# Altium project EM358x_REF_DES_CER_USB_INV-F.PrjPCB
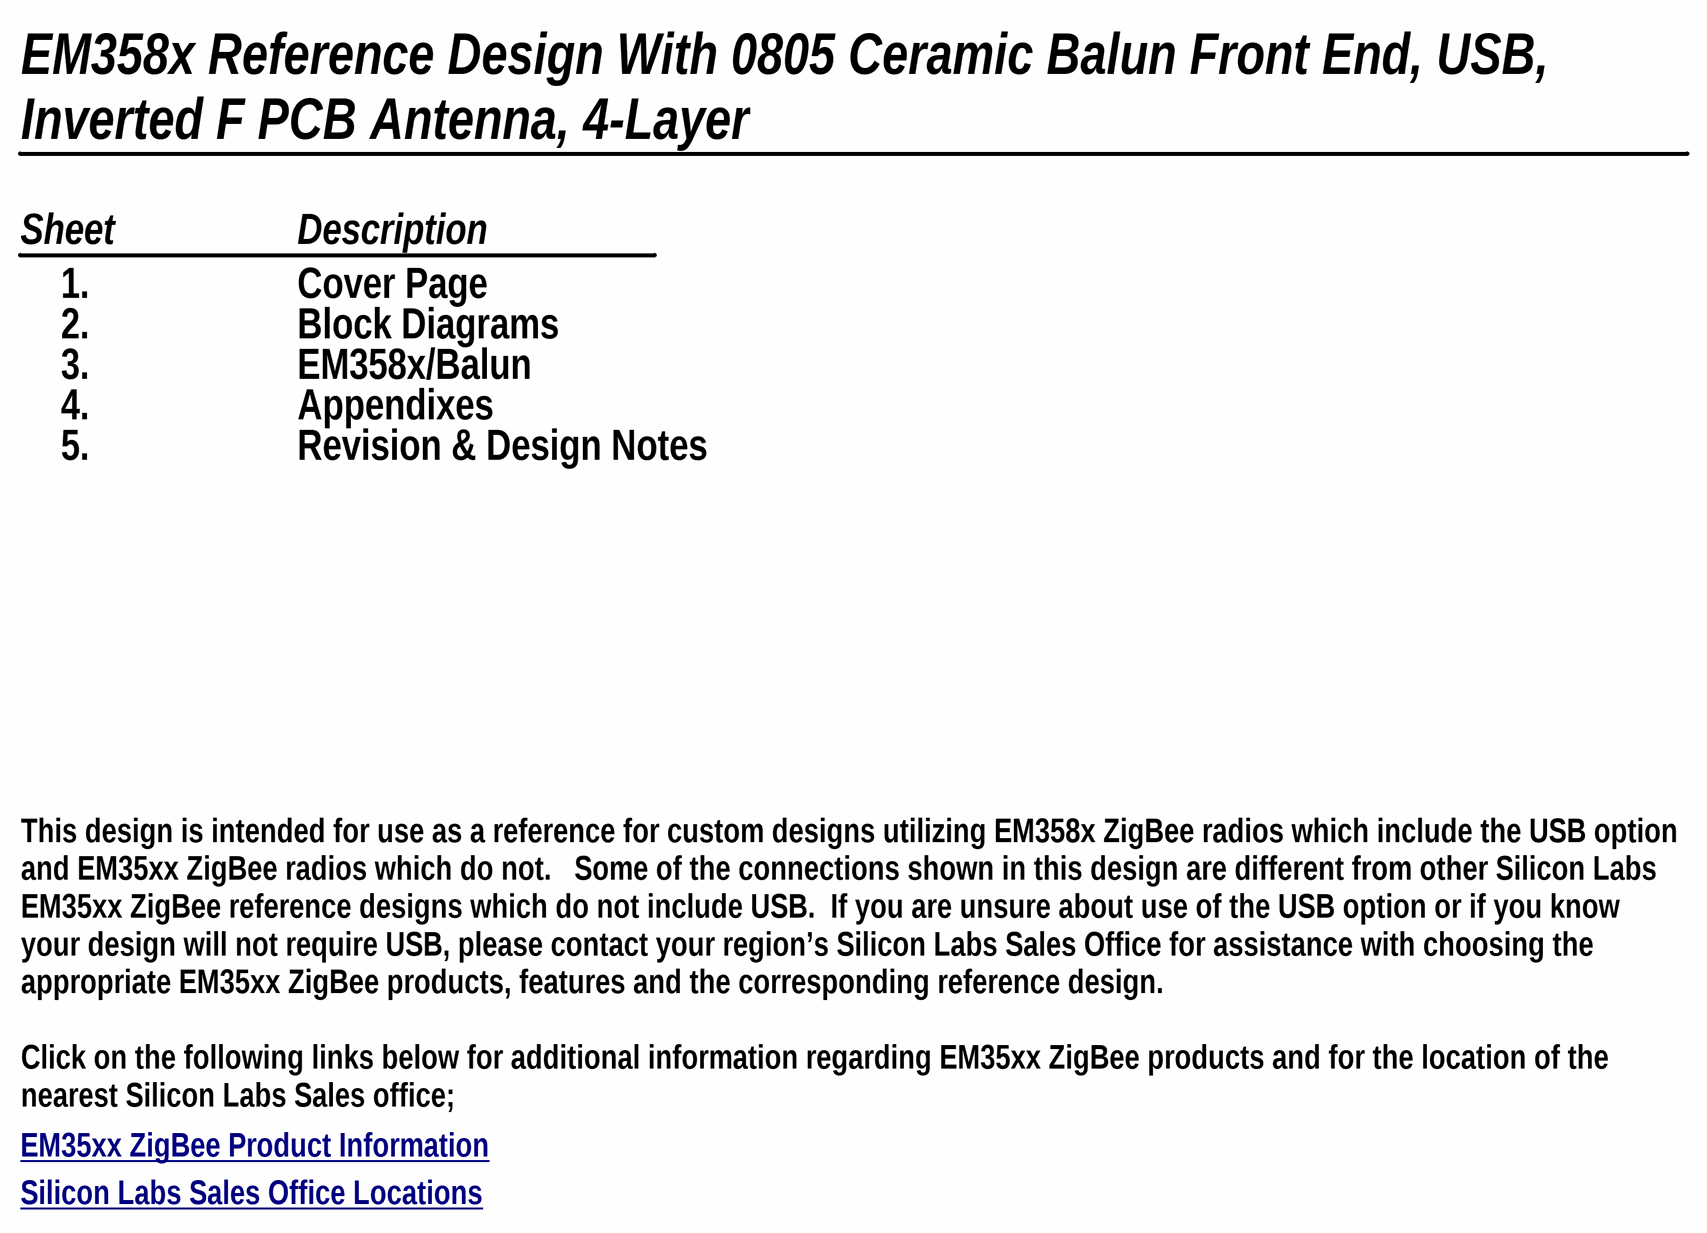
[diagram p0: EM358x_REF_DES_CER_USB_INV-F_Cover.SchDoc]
Title: Ceramic Balun W/USB 4 Layer Ref.Design; Company Web Site: www.silabs.com; Company Tel: 617-951-0200; Company Design Group: Embedded Systems Applications Engineering Group; Company Address 3: Boston, MA 02210; Company Address 2: 2nd Floor; Company Address 1: 25 Thomson Place; ClassName: PCB Only; Board Rev: A0; Board No: EM358x_REF_DES_CER_USB_INV-F
5 sheets, 71 parts. Net scope: global (net labels, ports and power ports of the same name join across sheets).
Board file: EM358x_REF_DES_CER_USB_INV-F.PcbDoc
Sheets:
  EM358x_REF_DES_CER_USB_INV-F_Cover.SchDoc
  EM358x_REF_DES_CER_USB_INV-F_Block.SchDoc
  EM358x_REF_DES_CER_USB_INV-F_Main.SchDoc
  EM358x_REF_DES_CER_USB_INV-F_App.SchDoc
  EM358x_REF_DES_CER_USB_INV-F_Rev_Notes.SchDoc

## Sheet EM358x_REF_DES_CER_USB_INV-F_Cover.SchDoc: EM358x/0805 Ceramic Balun W/USB Reference Design
size C; Organization: MCU & Wireless Division Simplicity Support Group; Address1: 25 Thomson Place, 2nd Floor; Address2: Boston, MA 02210, USA; Address3: www.silabs.com; Address4: 617-951-0200; Revision: A0; SheetNumber: 1; SheetTotal: 5

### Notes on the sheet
- EM358x Reference Design With 0805 Ceramic Balun Front End, USB, Inverted F PCB Antenna, 4-Layer
- Sheet
- 1.
- Description
- Cover Page
- 2.
- Block Diagrams
- 3.
- 4.
- EM358x/Balun
- Appendixes
- 5.
- Revision & Design Notes
- This design is intended for use as a reference for custom designs utilizing EM358x ZigBee radios which include the USB option and EM35xx ZigBee radios which do not.   Some of the connections shown in this design are different from other Silicon Labs EM35xx ZigBee reference designs which do not include USB.  If you are unsure about use of the USB option or if you know your design will not require USB, please contact your region’s Silicon Labs Sales Office for assistance with choosing the appropriate EM35xx ZigBee products, features and the corresponding reference design.
  Click on the following links below for additional information regarding EM35xx ZigBee products and for the location of the nearest Silicon Labs Sales office;
- EM35xx ZigBee Product Information <http://www.silabs.com/products/wireless/zigbee/Pages/default.aspx>
- Silicon Labs Sales Office Locations <http://www.silabs.com/buysample/pages/contact-sales.aspx>

## Sheet EM358x_REF_DES_CER_USB_INV-F_Block.SchDoc: EM358x/0805 Ceramic Balun W/USB Reference Design
size C; Organization: MCU & Wireless Division Simplicity Support Group; Address1: 25 Thomson Place, 2nd Floor; Address2: Boston, MA 02210, USA; Address3: www.silabs.com; Address4: 617-951-0200; Revision: A0; SheetNumber: 2; SheetTotal: 5
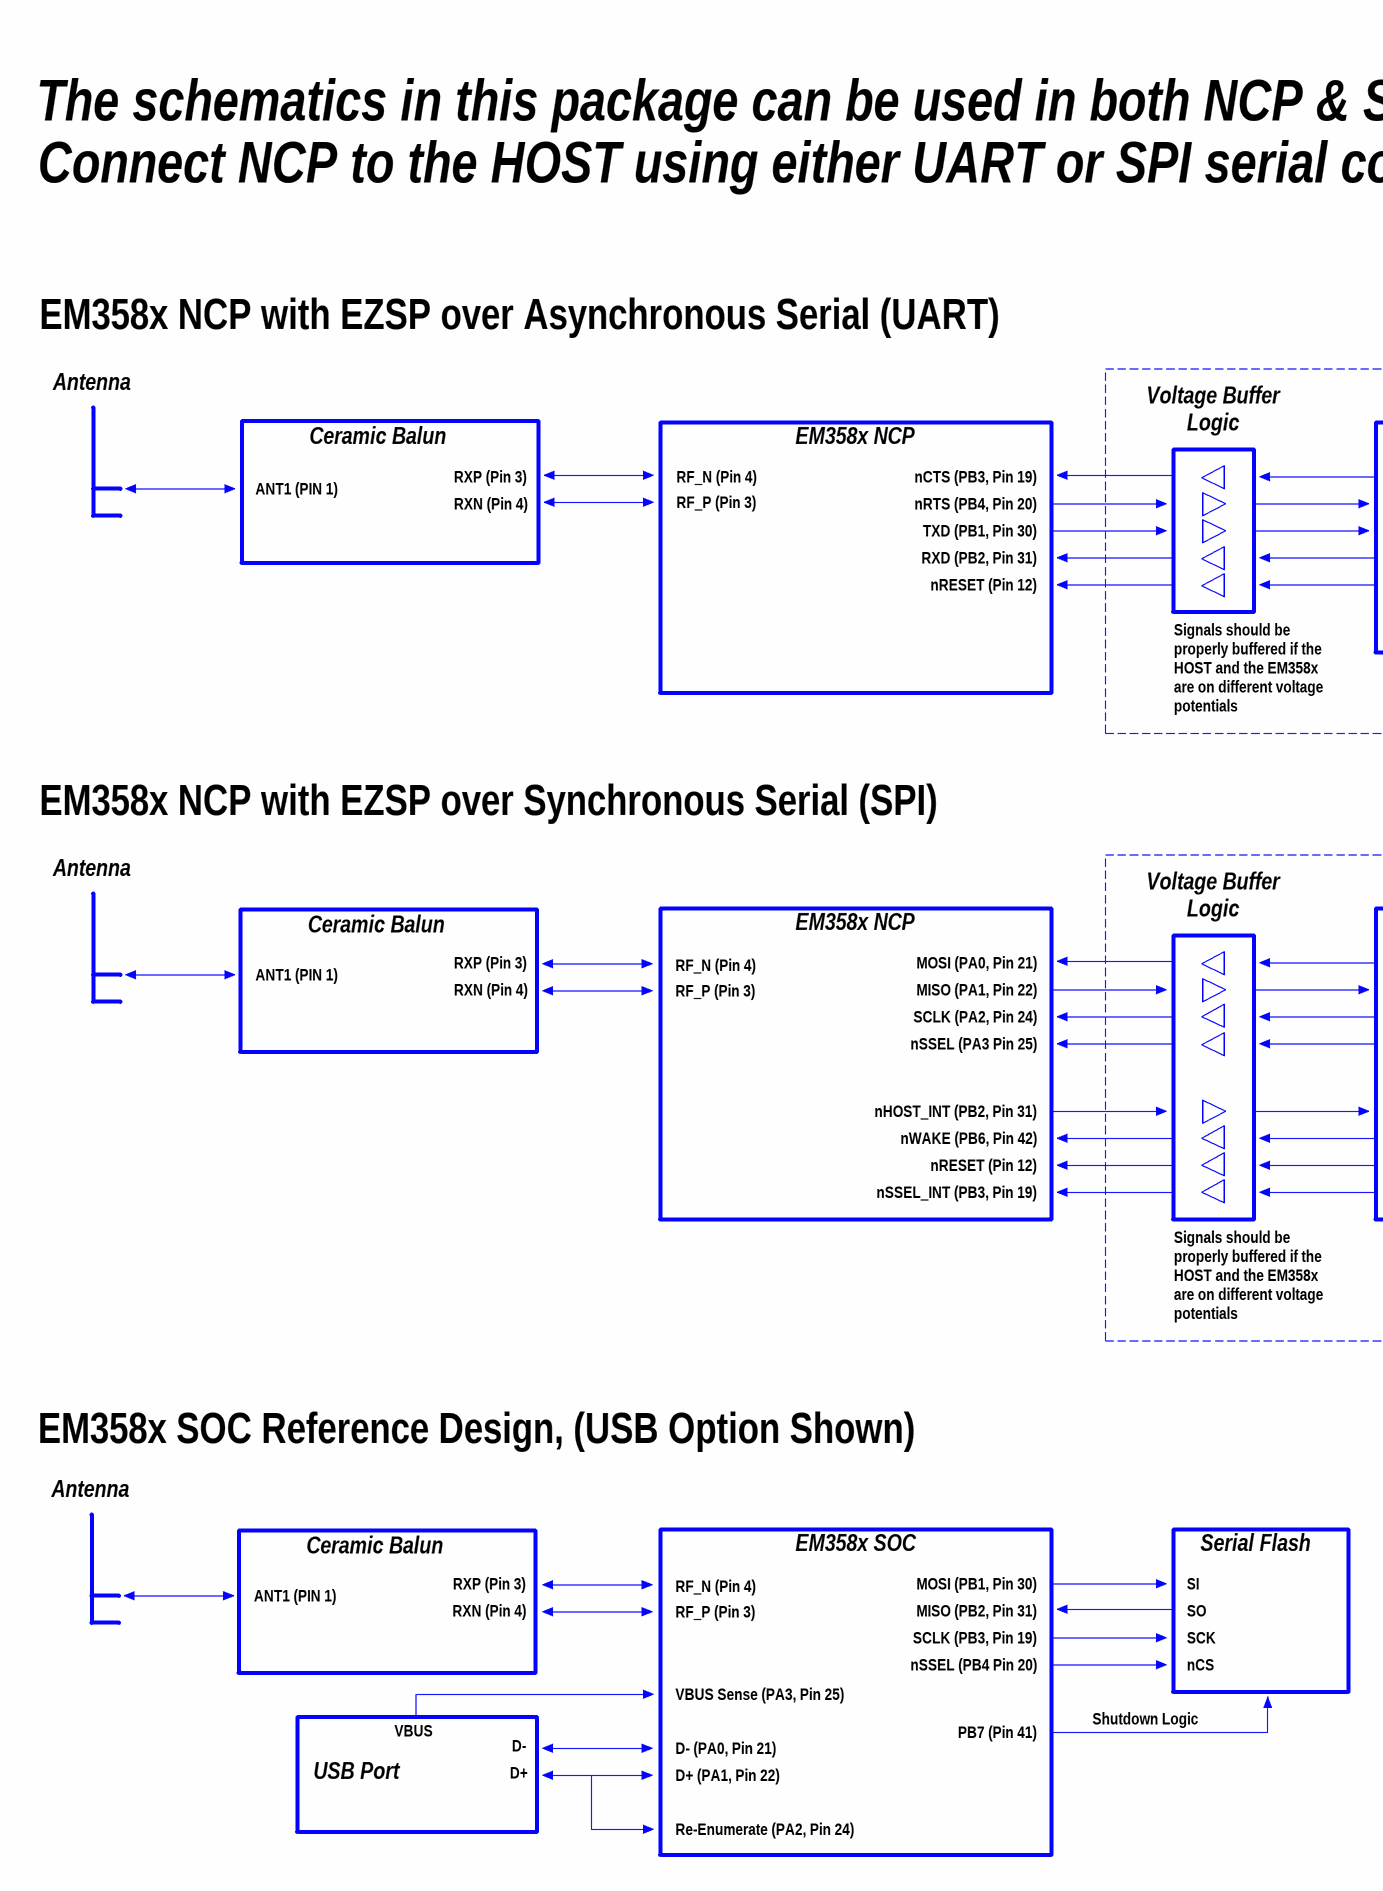
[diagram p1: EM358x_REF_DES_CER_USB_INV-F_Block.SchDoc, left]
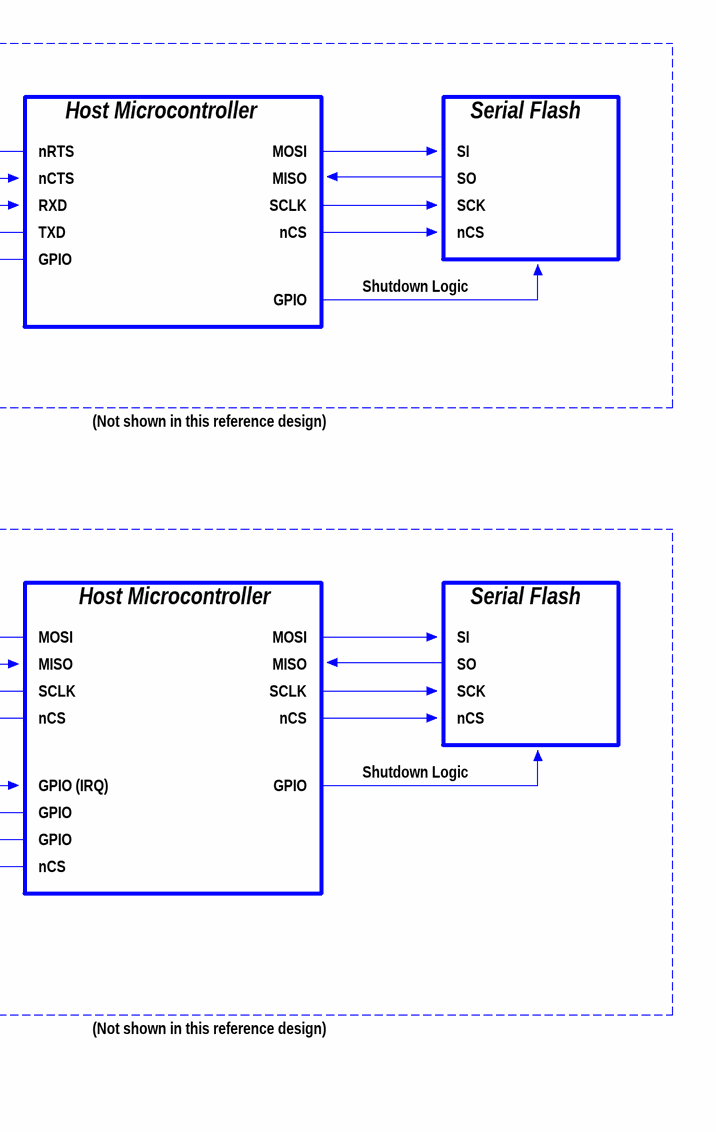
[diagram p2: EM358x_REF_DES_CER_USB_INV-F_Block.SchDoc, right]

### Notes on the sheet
- The schematics in this package can be used in both NCP & SOC designs involving the EM358x.
- Connect NCP to the HOST using either UART or SPI serial connection as shown below.
- EM358x NCP with EZSP over Asynchronous Serial (UART)
- Antenna
- Voltage Buffer
- Logic
- ANT1 (PIN 1)
- Ceramic Balun
- RXP (Pin 3)
- RF_N (Pin 4)
- EM358x NCP
- nCTS (PB3, Pin 19)
- nRTS
- Host Microcontroller
- MOSI
- SI
- Serial Flash
- RXN (Pin 4)
- RF_P (Pin 3)
- nRTS (PB4, Pin 20)
- TXD (PB1, Pin 30)
- RXD (PB2, Pin 31)
- nCTS
- RXD
- TXD
- MISO
- SCLK
- nCS
- SO
- SCK
- nRESET (Pin 12)
- GPIO
- Shutdown Logic
- Signals should be properly buffered if the HOST and the EM358x are on different voltage potentials
- (Not shown in this reference design)
- EM358x NCP with EZSP over Synchronous Serial (SPI)
- MOSI (PA0, Pin 21)
- MISO (PA1, Pin 22)
- SCLK (PA2, Pin 24)
- nSSEL (PA3 Pin 25)
- nHOST_INT (PB2, Pin 31)
- nWAKE (PB6, Pin 42)
- GPIO (IRQ)
- nSSEL_INT (PB3, Pin 19)
- EM358x SOC Reference Design, (USB Option Shown)
- EM358x SOC
- MOSI (PB1, Pin 30)
- MISO (PB2, Pin 31)
- SCLK (PB3, Pin 19)
- VBUS Sense (PA3, Pin 25)
- nSSEL (PB4 Pin 20)
- USB Port
- VBUS
- D-
- D+
- D- (PA0, Pin 21)
- D+ (PA1, Pin 22)
- PB7 (Pin 41)
- Re-Enumerate (PA2, Pin 24)

## Sheet EM358x_REF_DES_CER_USB_INV-F_Main.SchDoc: EM358x/0805 Ceramic Balun W/USB Reference Design
size C; Organization: MCU & Wireless Division Simplicity Support Group; Address1: 25 Thomson Place, 2nd Floor; Address2: Boston, MA 02210, USA; Address3: www.silabs.com; Address4: 617-951-0200; Revision: A0; SheetNumber: 3; SheetTotal: 5
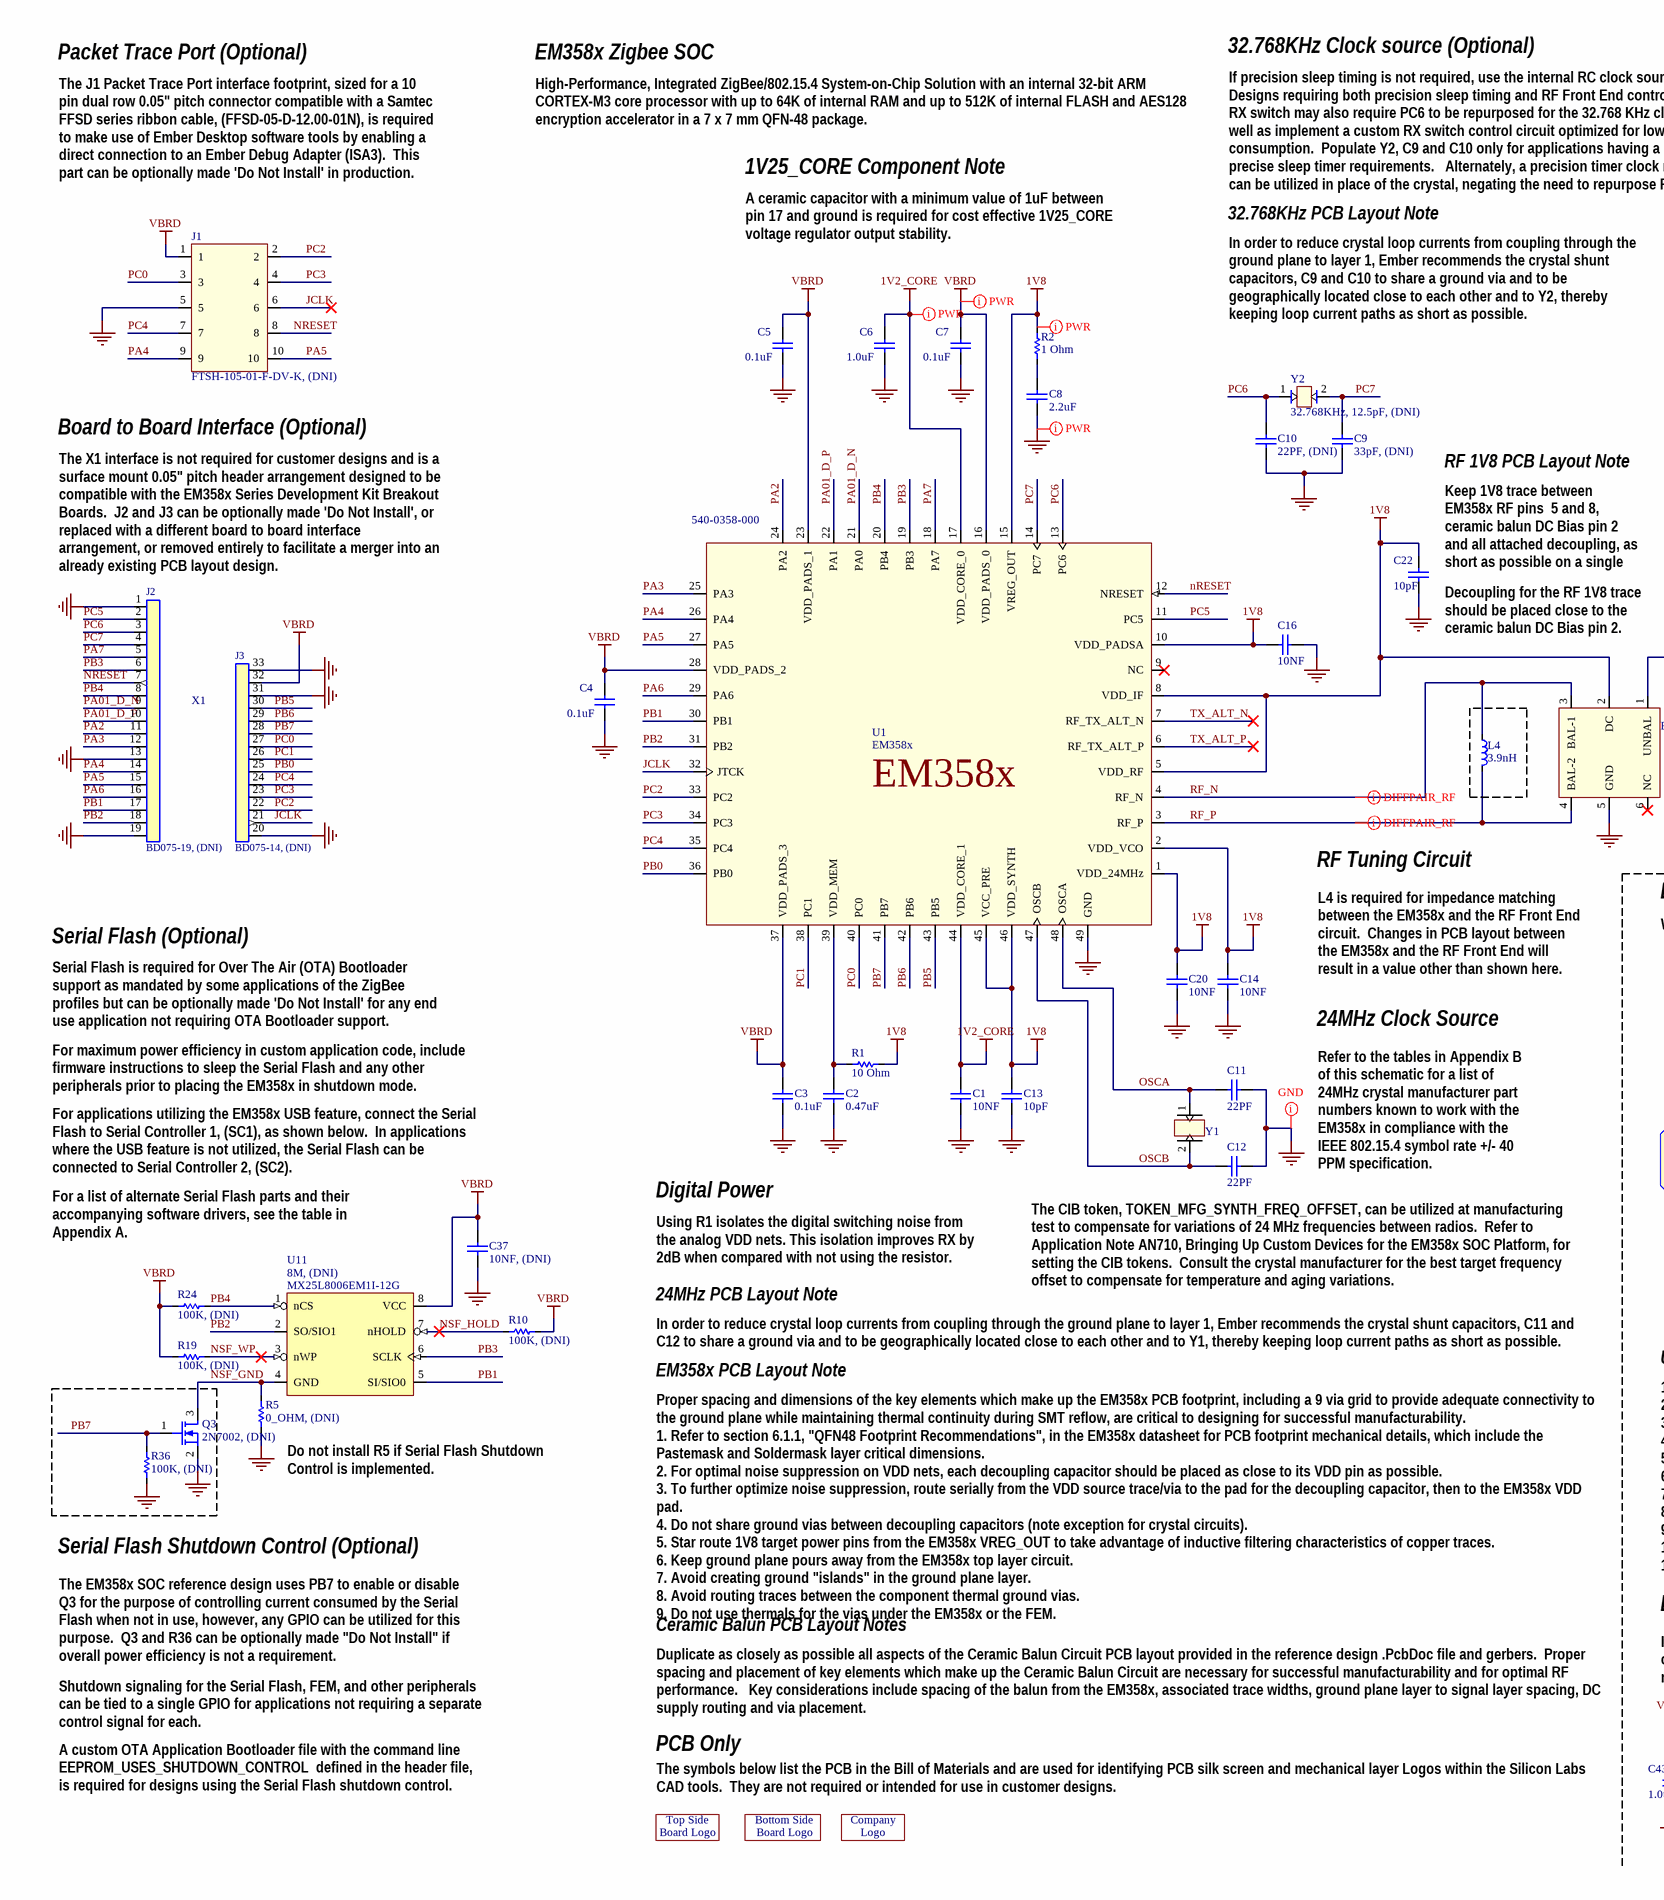
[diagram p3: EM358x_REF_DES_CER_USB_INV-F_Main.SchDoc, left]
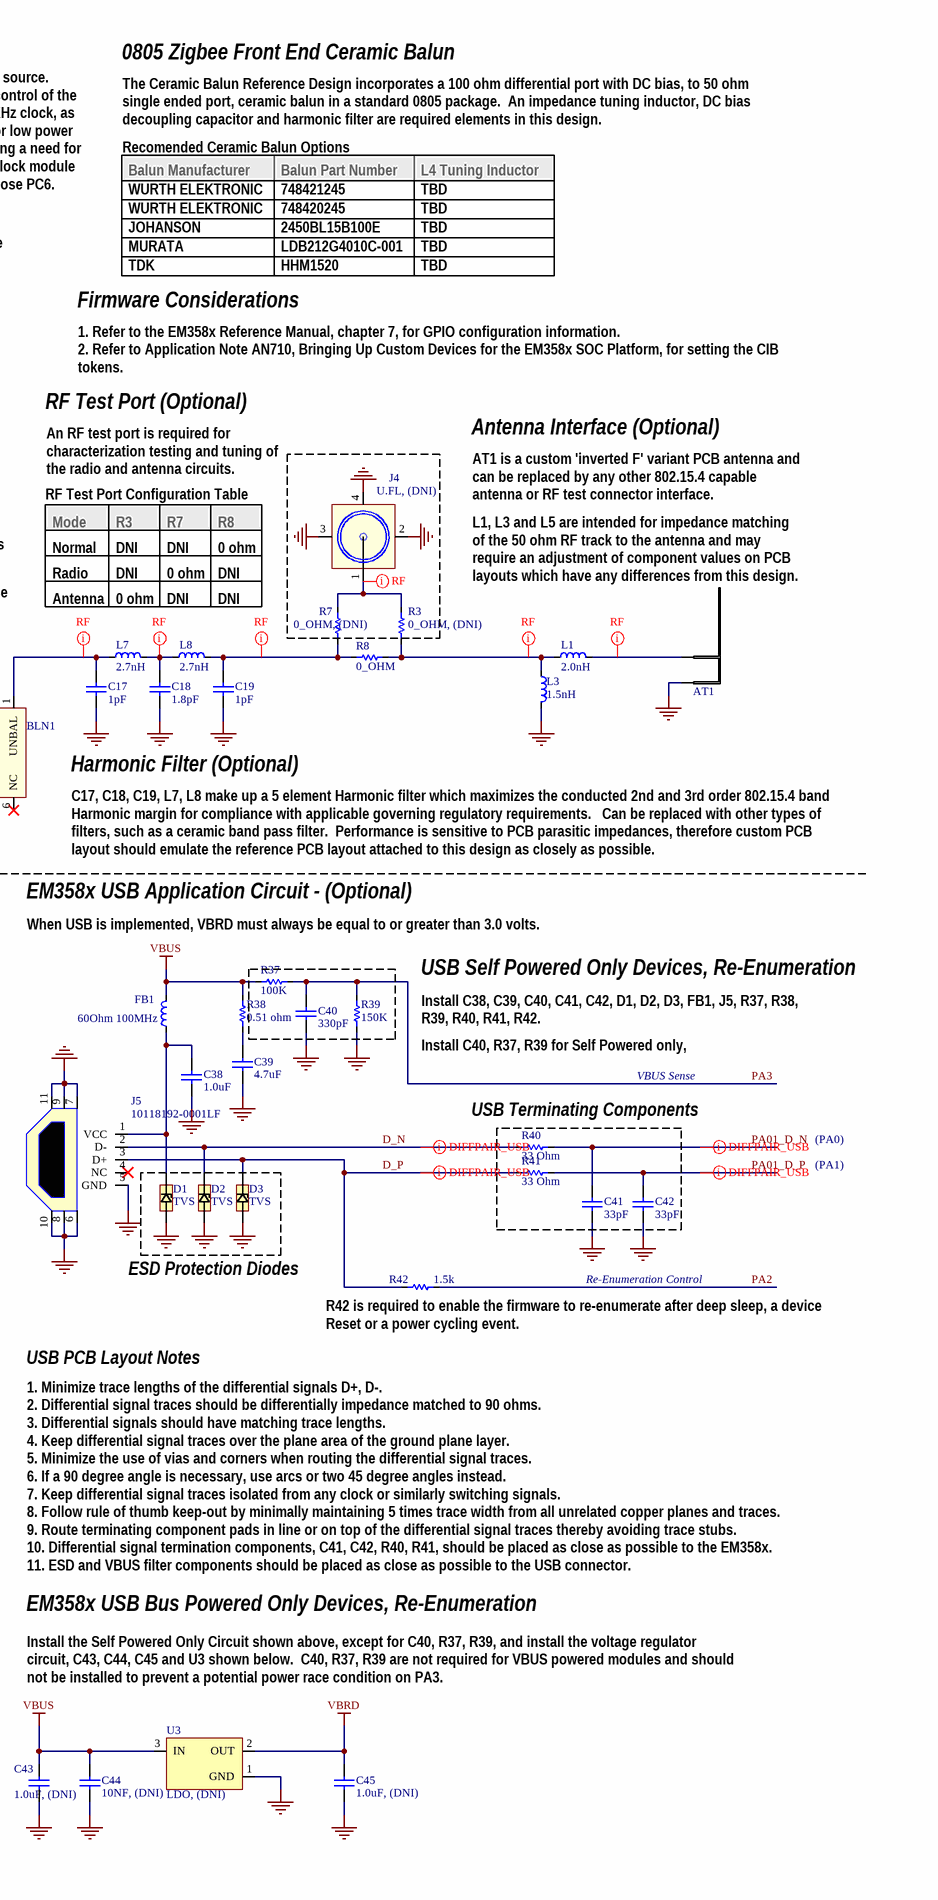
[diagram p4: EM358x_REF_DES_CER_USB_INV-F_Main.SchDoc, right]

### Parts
AT1  Copper Trace  [INVERTED_F_062_SM]  (value not drawn)  (no BOM)
BLN1  CHIP MULTILAYER CERAMIC, 2.4 GHZ. 50/100 Ohm  [BLN_0805]  (value not drawn)
C1  10NF  [C_0402]
C2  0.47uF  [C_0402]
C3  0.1uF  [C_0402]
C4  0.1uF  [C_0402]
C5  0.1uF  [C_0402]
C6  1.0uF  [C_0603]
C7  0.1uF  [C_0402]
C8  2.2uF  [C_0603]
C9  33pF, (DNI)  [C_0402]
C10  22PF, (DNI)  [C_0402]
C11  22PF  [C_0402]
C12  22PF  [C_0402]
C13  10pF  [C_0402]
C14  10NF  [C_0402]
C16  10NF  [C_0402]
C17  1pF  [C_0402]
C18  1.8pF  [C_0402]
C19  1pF  [C_0402]
C20  10NF  [C_0402]
C22  10pF  [C_0402]
C37  10NF, (DNI)  [C_0402]
C38  1.0uF  [C_0603]
C39  4.7uF  [C_0603]
C40  330pF  [C_0402]
C41  33pF  [C_0402]
C42  33pF  [C_0402]
C43  1.0uF, (DNI)  [C_0603]
C44  10NF, (DNI)  [C_0402]
C45  1.0uF, (DNI)  [C_0603]
D1  TVS  [TVS_0402]
D2  TVS  [TVS_0402]
D3  TVS  [TVS_0402]
FB1  60Ohm 100MHz  [L_0603]
J1  FTSH-105-01-F-DV-K, (DNI)  [610-0019-000-REF-DES]
J2  BD075-19, (DNI)  (mechanical)
J3  BD075-14, (DNI)  (mechanical)
J4  U.FL, (DNI)  [UFL-R-SMT_1]
J5  10118192-0001LF  [FCI_10118192-0001LF]
L1  2.0nH  [L_0402]
L3  1.5nH  [L_0402]
L4  3.9nH  [L_0603]
L7  2.7nH  [L_0402]
L8  2.7nH  [L_0402]
LOGO1  SiliconLabsLogo_100  [SiliconLabsLogo_100_Mech-16]  (value not drawn)  (no BOM)
PCB1  EM35x Ceramic Balun 4 Layer Reference Design w/USB, Inverted F, Corporate Logo  [710-0651-006]  (value not drawn)
PCB2  Bottom Silk Screen ID and RoHS Text  [710-0651-006_ROHS]  (value not drawn)  (no BOM)
Q3  2N7002, (DNI)  [SOT23-3L]
R1  10 Ohm  [R_0402]
R2  1 Ohm  [R_0402]
R3  0_OHM, (DNI)  [R_0402]
R5  0_OHM, (DNI)  [R_0402]
R7  0_OHM, (DNI)  [R_0402]
R8  0_OHM  [R_0402]
R10  100K, (DNI)  [R_0402]
R19  100K, (DNI)  [R_0402]
R24  100K, (DNI)  [R_0402]
R36  100K, (DNI)  [R_0402]
R37  100K  [R_0402]
R38  0.51 ohm  [R_0402]
R39  150K  [R_0402]
R40  33 Ohm  [R_0402]
R41  33 Ohm  [R_0402]
R42  1.5k  [R_0402]
U1  EM358x  PART_NUMBER: 540-0358-000  [EM357]
U3  LDO, (DNI)  [TSOP95P280X90-3N]
U11  8M, (DNI)  Part: MX25L8006EM1I-12G  [SOIC127P600-8M]
X1  Dual Row Socket, (DNI)  [EM35X_RCM_MODULE_SIDE_SMT]  (value not drawn)  (no BOM)
Y1  24.000MHZ, 18PF LOAD  [HC-49-SMD]  (value not drawn)
Y2  32.768KHz, 12.5pF, (DNI)  [IL3X]

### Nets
1V2_CORE: C1.1 C6.1 U1.17(VDD_CORE_0) U1.44(VDD_CORE_1)
1V8: BLN1.2(DC) C13.1 C14.1 C16.1 C20.1 C22.1 R1.1 R2.1 U1.1(VDD_24MHz) U1.2(VDD_VCO) U1.5(VDD_RF) U1.8(VDD_IF) U1.10(VDD_PADSA) U1.15(VREG_OUT) U1.45(VCC_PRE) U1.46(VDD_SYNTH)
GND: AT1.2(GND) BLN1.5(GND) C1.2 C2.2 C3.2 C4.2 C5.2 C6.2 C7.2 C8.2 C9.2 C10.2 C11.2 C12.2 C13.2 C14.2 C16.2 C17.2 C18.2 C19.2 C20.2 C22.2 C37.2 C38.2 C39.2 C40.2 C41.2 C42.2 C43.2 C44.2 C45.2 D1.1 D2.1 D3.1 J1.5 J4.2(GND) J4.3(GND) J4.4(GND) J5.5(GND) J5.6 J5.7 J5.8 J5.9 J5.10 J5.11 L3.2 Q3.2(S) R5.2 R36.2 R39.2 U1.49(GND) U3.1(GND) X1.1(GND) X1.13(GND) X1.19(GND) X1.20(GND) X1.31(GND) X1.33(GND)
VBRD: C3.1 C4.1 C5.1 C7.1 C37.1 C45.1 J1.1 R10.2 R19.2 R24.2 U1.16(VDD_PADS_0) U1.23(VDD_PADS_1) U1.28(VDD_PADS_2) U1.37(VDD_PADS_3) U3.2(OUT) U11.8(VCC) X1.32(VBRD)
VBUS: C43.1 C44.1 FB1.2 R37.1 R38.2 U3.3(IN)
D_N: D2.2 J5.2(D-) R40.1
D_P: D3.2 J5.3(D+) R41.1 R42.1
JCLK: J1.6 U1.32(JTCK) X1.21(JCLK)
nRESET: J1.8 U1.12(NRESET) X1.7(nRESET)
NSF_GND: Q3.3(D) R5.1 U11.4(GND)
NSF_HOLD: R10.1 U11.7(nHOLD)
NSF_WP: R19.1 U11.3(nWP)
OSCA: C11.1 U1.48(OSCA) Y1.1(OSCB)
OSCB: C12.1 U1.47(OSCB) Y1.2(OSCA)
PA01_D_N: C41.1 R40.2 U1.21(PA0) X1.9(PA0)
PA01_D_P: C42.1 R41.2 U1.22(PA1) X1.10(PA1)
PA2: R42.2 U1.24(PA2) X1.11(PA2)
PA3: C40.1 R37.2 R39.1 U1.25(PA3) X1.12(PA3)
PA4: J1.9 U1.26(PA4) X1.14(PA4)
PA5: J1.10 U1.27(PA5) X1.15(PA5)
PA6: U1.29(PA6) X1.16(PA6)
PA7: U1.18(PA7) X1.5(PA7)
PB0: U1.36(PB0) X1.25(PB0)
PB1: U1.30(PB1) U11.5(SI/SIO0) X1.17(PB1)
PB2: U1.31(PB2) U11.2(SO/SIO1) X1.18(PB2)
PB3: U1.19(PB3) U11.6(SCLK) X1.6(PB3)
PB4: R24.1 U1.20(PB4) U11.1(nCS) X1.8(PB4)
PB5: U1.43(PB5) X1.30(PB5)
PB6: U1.42(PB6) X1.29(PB6)
PB7: Q3.1(G) R36.1 U1.41(PB7) X1.28(PB7)
PC0: J1.3 U1.40(PC0) X1.27(PC0)
PC1: U1.38(PC1) X1.26(PC1)
PC2: J1.2 U1.33(PC2) X1.22(PC2)
PC3: J1.4 U1.34(PC3) X1.23(PC3)
PC4: J1.7 U1.35(PC4) X1.24(PC4)
PC5: U1.11(PC5) X1.2(PC5)
PC6: C10.1 U1.13(PC6) X1.3(PC6) Y2.1
PC7: C9.1 U1.14(PC7) X1.4(PC7) Y2.2
RF_N: BLN1.3(BAL-1) L4.1 U1.4(RF_N)
RF_P: BLN1.4(BAL-2) L4.2 U1.3(RF_P)
TX_ALT_N: U1.7(RF_TX_ALT_N)
TX_ALT_P: U1.6(RF_TX_ALT_P)
NetAT1_1: AT1.1(ANT) L1.2
NetBLN1_1: BLN1.1(UNBAL) C17.1 L7.1
NetC2_1: C2.1 R1.2 U1.39(VDD_MEM)
NetC8_1: C8.1 R2.2
NetC18_1: C18.1 L7.2 L8.1
NetC19_1: C19.1 L8.2 R7.1 R8.1
NetC38_1: C38.1 D1.2 FB1.1 J5.1(VCC)
NetC39_1: C39.1 R38.1
NetJ4_1: J4.1(SIGNAL) R3.2 R7.2
NetL1_1: L1.1 L3.1 R3.1 R8.2

Not connected (* = marked no-connect by the designer): BLN1 6(NC)*; J5 4(NC)*; U1 9(NC)*

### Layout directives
rule Width Constraint [Pref Width = 20mil    Min Width = 5mil    Max Width = 40mil]: 1V2_CORE, 1V8, VBRD
rule Width Constraint [Pref Width = 28mil    Min Width = 6mil    Max Width = 60mil]; rule Clearance Constraint [Clearance = 6mil]: NetAT1_1, NetBLN1_1, NetC18_1, NetC19_1, NetJ4_1, NetL1_1
differential pair; rule Width Constraint [Pref Width = 7mil    Min Width = 5mil    Max Width = 10mil]; rule Matched Net Lengths [Tolerance = 2.5mil]: RF_N, RF_P
rule Clearance Constraint [Clearance = 9.5mil]: GND
rule Width Constraint [Pref Width = 20mil    Min Width = 5mil    Max Width = 40mil]; rule Short-Circuit Constraint [Short Circuit - Allowed]: GND
rule Differential Pairs Routing [Pref Gap = 9mil    Min Gap  = 8mil    Max Gap  = 50mil]; rule Matched Net Lengths [Tolerance = 100mil]; differential pair; rule Width Constraint [Pref Width = 12mil    Min Width = 6mil    Max Width = 60mil]: D_N, D_P, PA01_D_N, PA01_D_P

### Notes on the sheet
- Packet Trace Port (Optional)
- EM358x Zigbee SOC
- 32.768KHz Clock source (Optional)
- 0805 Zigbee Front End Ceramic Balun
- High-Performance, Integrated ZigBee/802.15.4 System-on-Chip Solution with an internal 32-bit ARM CORTEX-M3 core processor with up to 64K of internal RAM and up to 512K of internal FLASH and AES128 encryption accelerator in a 7 x 7 mm QFN-48 package.
- The Ceramic Balun Reference Design incorporates a 100 ohm differential port with DC bias, to 50 ohm single ended port, ceramic balun in a standard 0805 package.  An impedance tuning inductor, DC bias decoupling capacitor and harmonic filter are required elements in this design.
- Recomended Ceramic Balun Options
- The J1 Packet Trace Port interface footprint, sized for a 10 pin dual row 0.05" pitch connector compatible with a Samtec FFSD series ribbon cable, (FFSD-05-D-12.00-01N), is required to make use of Ember Desktop software tools by enabling a direct connection to an Ember Debug Adapter (ISA3).  This part can be optionally made 'Do Not Install' in production.
- 1V25_CORE Component Note
- If precision sleep timing is not required, use the internal RC clock source.  Designs requiring both precision sleep timing and RF Front End control of the RX switch may also require PC6 to be repurposed for the 32.768 KHz clock, as well as implement a custom RX switch control circuit optimized for low power consumption.  Populate Y2, C9 and C10 only for applications having a need for precise sleep timer requirements.   Alternately, a precision timer clock module can be utilized in place of the crystal, negating the need to repurpose PC6.
- WURTH ELEKTRONIC
- Balun Manufacturer
- 748421245
- Balun Part Number
- L4 Tuning Inductor
- TBD
- A ceramic capacitor with a minimum value of 1uF between pin 17 and ground is required for cost effective 1V25_CORE voltage regulator output stability.
- 32.768KHz PCB Layout Note
- JOHANSON
- MURATA
- TDK
- 2450BL15B100E
- 748420245
- LDB212G4010C-001
- HHM1520
- In order to reduce crystal loop currents from coupling through the ground plane to layer 1, Ember recommends the crystal shunt capacitors, C9 and C10 to share a ground via and to be geographically located close to each other and to Y2, thereby keeping loop current paths as short as possible.
- Firmware Considerations
- 1. Refer to the EM358x Reference Manual, chapter 7, for GPIO configuration information.
  2. Refer to Application Note AN710, Bringing Up Custom Devices for the EM358x SOC Platform, for setting the CIB tokens.
  3. Set TOKEN_MFG_PHY_CONFIG value to FE to enable the correct RF path and RX Boost mode for this reference design.
- Board to Board Interface (Optional)
- RF Test Port (Optional)
- Antenna Interface (Optional)
- RF 1V8 PCB Layout Note
- An RF test port is required for characterization testing and tuning of the radio and antenna circuits.
- (near J4) RF Test Port Configuration Table
- Mode
- R3
- R7
- R8
- AT1 is a custom 'inverted F' variant PCB antenna and can be replaced by any other 802.15.4 capable antenna or RF test connector interface.
- (near X1) The X1 interface is not required for customer designs and is a surface mount 0.05" pitch header arrangement designed to be compatible with the EM358x Series Development Kit Breakout Boards.  J2 and J3 can be optionally made 'Do Not Install', or replaced with a different board to board interface arrangement, or removed entirely to facilitate a merger into an already existing PCB layout design.
- (near C22) Keep 1V8 trace between EM358x RF pins  5 and 8, ceramic balun DC Bias pin 2 and all attached decoupling, as short as possible on a single layer.
- Radio
- Normal
- DNI
- 0 ohm
- L1, L3 and L5 are intended for impedance matching of the 50 ohm RF track to the antenna and may require an adjustment of component values on PCB layouts which have any differences from this design.
- (near C22) Decoupling for the RF 1V8 trace should be placed close to the ceramic balun DC Bias pin 2.
- Antenna
- Harmonic Filter (Optional)
- RF Tuning Circuit
- EM358x USB Application Circuit - (Optional)
- C17, C18, C19, L7, L8 make up a 5 element Harmonic filter which maximizes the conducted 2nd and 3rd order 802.15.4 band Harmonic margin for compliance with applicable governing regulatory requirements.   Can be replaced with other types of filters, such as a ceramic band pass filter.  Performance is sensitive to PCB parasitic impedances, therefore custom PCB layout should emulate the reference PCB layout attached to this design as closely as possible.
- (near J2) Serial Flash (Optional)
- L4 is required for impedance matching between the EM358x and the RF Front End circuit.  Changes in PCB layout between the EM358x and the RF Front End will result in a value other than shown here.
- When USB is implemented, VBRD must always be equal to or greater than 3.0 volts.
- (near J2) Serial Flash is required for Over The Air (OTA) Bootloader support as mandated by some applications of the ZigBee profiles but can be optionally made 'Do Not Install' for any end use application not requiring OTA Bootloader support.
- 24MHz Clock Source
- USB Self Powered Only Devices, Re-Enumeration
- Install C38, C39, C40, C41, C42, D1, D2, D3, FB1, J5, R37, R38, R39, R40, R41, R42.
- For maximum power efficiency in custom application code, include firmware instructions to sleep the Serial Flash and any other peripherals prior to placing the EM358x in shutdown mode.
- Install C40, R37, R39 for Self Powered only, otherwise DNI
- VBUS Sense
- Refer to the tables in Appendix B of this schematic for a list of 24MHz crystal manufacturer part numbers known to work with the EM358x in compliance with the IEEE 802.15.4 symbol rate +/- 40 PPM specification.
- (near R40) USB Terminating Components
- (PA0)
- (PA1)
- For applications utilizing the EM358x USB feature, connect the Serial Flash to Serial Controller 1, (SC1), as shown below.  In applications where the USB feature is not utilized, the Serial Flash can be connected to Serial Controller 2, (SC2).
- Digital Power
- For a list of alternate Serial Flash parts and their accompanying software drivers, see the table in Appendix A.
- Using R1 isolates the digital switching noise from the analog VDD nets. This isolation improves RX by 2dB when compared with not using the resistor.
- (near C12) The CIB token, TOKEN_MFG_SYNTH_FREQ_OFFSET, can be utilized at manufacturing test to compensate for variations of 24 MHz frequencies between radios.  Refer to Application Note AN710, Bringing Up Custom Devices for the EM358x SOC Platform, for setting the CIB tokens.  Consult the crystal manufacturer for the best target frequency offset to compensate for temperature and aging variations.
- ESD Protection Diodes
- Re-Enumeration Control
- In order to reduce crystal loop currents from coupling through the ground plane to layer 1, Ember recommends the crystal shunt capacitors, C11 and C12 to share a ground via and to be geographically located close to each other and to Y1, thereby keeping loop current paths as short as possible.
- 24MHz PCB Layout Note
- (near R42) R42 is required to enable the firmware to re-enumerate after deep sleep, a device Reset or a power cycling event.
- EM358x PCB Layout Note
- USB PCB Layout Notes
- (near R5) Do not install R5 if Serial Flash Shutdown Control is implemented.
- Serial Flash Shutdown Control (Optional)
- Proper spacing and dimensions of the key elements which make up the EM358x PCB footprint, including a 9 via grid to provide adequate connectivity to the ground plane while maintaining thermal continuity during SMT reflow, are critical to designing for successful manufacturability.
  1. Refer to section 6.1.1, "QFN48 Footprint Recommendations", in the EM358x datasheet for PCB footprint mechanical details, which include the Pastemask and Soldermask layer critical dimensions.
  2. For optimal noise suppression on VDD nets, each decoupling capacitor should be placed as close to its VDD pin as possible.
  3. To further optimize noise suppression, route serially from the VDD source trace/via to the pad for the decoupling capacitor, then to the EM358x VDD pad.
  4. Do not share ground vias between decoupling capacitors (note exception for crystal circuits).
  5. Star route 1V8 target power pins from the EM358x VREG_OUT to take advantage of inductive filtering characteristics of copper traces.
  6. Keep ground plane pours away from the EM358x top layer circuit.
  7. Avoid creating ground "islands" in the ground plane layer.
  8. Avoid routing traces between the component thermal ground vias.
  9. Do not use thermals for the vias under the EM358x or the FEM.
- 1. Minimize trace lengths of the differential signals D+, D-.
  2. Differential signal traces should be differentially impedance matched to 90 ohms.
  3. Differential signals should have matching trace lengths.
  4. Keep differential signal traces over the plane area of the ground plane layer.
  5. Minimize the use of vias and corners when routing the differential signal traces.
  6. If a 90 degree angle is necessary, use arcs or two 45 degree angles instead.
  7. Keep differential signal traces isolated from any clock or similarly switching signals.
  8. Follow rule of thumb keep-out by minimally maintaining 5 times trace width from all unrelated copper planes and traces.
  9. Route terminating component pads in line or on top of the differential signal traces thereby avoiding trace stubs.
  10. Differential signal termination components, C41, C42, R40, R41, should be placed as close as possible to the EM358x.
  11. ESD and VBUS filter components should be placed as close as possible to the USB connector.
- The EM358x SOC reference design uses PB7 to enable or disable Q3 for the purpose of controlling current consumed by the Serial Flash when not in use, however, any GPIO can be utilized for this purpose.  Q3 and R36 can be optionally made "Do Not Install" if overall power efficiency is not a requirement.
- Ceramic Balun PCB Layout Notes
- EM358x USB Bus Powered Only Devices, Re-Enumeration
- Shutdown signaling for the Serial Flash, FEM, and other peripherals can be tied to a single GPIO for applications not requiring a separate control signal for each.
- Duplicate as closely as possible all aspects of the Ceramic Balun Circuit PCB layout provided in the reference design .PcbDoc file and gerbers.  Proper spacing and placement of key elements which make up the Ceramic Balun Circuit are necessary for successful manufacturability and for optimal RF performance.   Key considerations include spacing of the balun from the EM358x, associated trace widths, ground plane layer to signal layer spacing, DC supply routing and via placement.
- Install the Self Powered Only Circuit shown above, except for C40, R37, R39, and install the voltage regulator circuit, C43, C44, C45 and U3 shown below.  C40, R37, R39 are not required for VBUS powered modules and should not be installed to prevent a potential power race condition on PA3.
- PCB Only
- The symbols below list the PCB in the Bill of Materials and are used for identifying PCB silk screen and mechanical layer Logos within the Silicon Labs CAD tools.  They are not required or intended for use in customer designs.
- A custom OTA Application Bootloader file with the command line  EEPROM_USES_SHUTDOWN_CONTROL  defined in the header file, is required for designs using the Serial Flash shutdown control.

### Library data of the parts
AT1 = 600-0PCB-ANT-F-62: Inverted F Antenna; Part Description: ANTENNA, PCB, COPPER TRACE, INVERTED F
BLN1 = 566-0075-000: Balun 0805; Part Description: BALUN, CHIP MULTILAYER CERAMIC, 2.4 GHZ. 50/100 OHM, -40C TO 85C, 0805 (2012 METRIC); MANUFACTURER: WURTH ELEKTRONIC, JOHANSON TECHNOLOGY, MURATA, TDK; PART_NUMBER: 748421245, 2450BL15B100E, LDB212G4010C-001, HHM1520; Temperature Coefficient: -40C to 85C
C1 C14 C20 = 550-0036-000: Part Description: CAPACITOR, CERAMIC, 10NF, +/-10%, 6.3V, -55C TO 125C, X7R, 0402 (1005 METRIC); MANUFACTURER: MURATA; PART_NUMBER: GRM155R70J103KA01D; VOLTAGE: 6.3V; TOLERANCE: +/-10%; Temperature Coefficient: -55C to 125C, X7R
C2 = 550-0037-000: Part Description: CAPACITOR, CERAMIC, 0.47UF, +/- 10%, 6.3V, -55C TO 85C, X5R, 0402 (1005 METRIC); MANUFACTURER: MURATA; PART_NUMBER: GRM155R60J474KE19D; VOLTAGE: 6.3V; TOLERANCE: +/- 10%; Temperature Coefficient: -55C to 85C, X5R
C3-C5 C7 = 550-0034-000: Part Description: CAPACITOR, CERAMIC, 0.1UF, +/-10%, 6.3V, -55C TO 125C, X7R, 0402 (1005 METRIC); MANUFACTURER: MURATA; PART_NUMBER: GRM155R70J104KA01D; VOLTAGE: 6.3V; TOLERANCE: +/-10%; Temperature Coefficient: -55C to 125C, X7R
C6 C38 = 550-0033-000: Part Description: CAPACITOR, CERAMIC, 1.0UF, +/-10%, 10V, -55C TO 125C, X7R, 0603 (1608 METRIC); MANUFACTURER: TAIYO YUDEN LTD; PART_NUMBER: LMK107B7105KA-T; VOLTAGE: 10V; TOLERANCE: +/-10%; Temperature Coefficient: -55C to 125C, X7R
C8 = 550-0038-000: Part Description: CAPACITOR, CERAMIC, 2.2UF, +/-10%, 6.3V, -55C TO 125C, X7R, 0603 (1608 METRIC); MANUFACTURER: MURATA; PART_NUMBER: CL10B225KQ8NNNC; VOLTAGE: 6.3V; TOLERANCE: +/-10%; Temperature Coefficient: -55C to 125C, X7R
C9 = 550-0039-000-DNI: Part Description: CAPACITOR, CERAMIC, 33PF, (DNI), +/-5%, 50V, -55C TO 125C, C0G, NP0, 0402 (1005 METRIC); MANUFACTURER: SAMSUNG ELECTRONICS; PART_NUMBER: CL05C330JB5NNNC; VOLTAGE: 50V; TOLERANCE: +/-5%; Temperature Coefficient: -55C to 125C, C0G, NP0
C10 = 550-2201-050-DNI: Part Description: CAPACITOR, CERAMIC, 22PF, (DNI), +/-5%, 50V, -55C TO 125C, 0402 (1005 METRIC); MANUFACTURER: MURATA; PART_NUMBER: GRM1555C1H220JA01D; VOLTAGE: 50V; TOLERANCE: +/-5%; Temperature Coefficient: -55C to 125C
C11 C12 = 550-2201-050: Part Description: CAPACITOR, CERAMIC, 22PF, +/-5%, 50V, -55C TO 125C, 0402 (1005 METRIC); MANUFACTURER: MURATA; PART_NUMBER: GRM1555C1H220JA01D; VOLTAGE: 50V; TOLERANCE: +/-5%; Temperature Coefficient: -55C to 125C
C13 C22 = 550-1001-050: Part Description: CAPACITOR, CERAMIC, 10PF, +/-5%, 50V, -55C TO 125C, 0402 (1005 METRIC); MANUFACTURER: MURATA; PART_NUMBER: GRM1555C1H100JA01D; VOLTAGE: 50V; TOLERANCE: +/-5%; Temperature Coefficient: -55C to 125C
C16 = 550-0036-000: Part Description: CAPACITOR, CERAMIC, 10NF, +/-10%, 6.3V, -55C TO 125C, X7R, 0402 (1005 METRIC); MANUFACTURER: MURATA; PART_NUMBER: GRM155R70J103KA01D; TOLERANCE: +/-10%; Temperature Coefficient: -55C to 125C, X7R; VOLTAGE: 6.3V
C17 C19 = 550-0040-000: Part Description: CAPACITOR, CERAMIC, 1PF, +/-0.25PF, 50V, -55C TO 125C, C0G, NP0, 0402 (1005 METRIC); MANUFACTURER: SAMSUNG ELECTRONICS; PART_NUMBER: CL05C010CB5NNNC; VOLTAGE: 50V; TOLERANCE: +/-0.25pF; Temperature Coefficient: -55C to 125C, C0G, NP0
C18 = 550-1P8A-050: Part Description: CAPACITOR, CERAMIC, 1.8PF, +/-0.25PF, 50V, -55C TO 125C, C0G, NP0, 0402 (1005 METRIC); MANUFACTURER: MURATA; PART_NUMBER: GRM1555C1H1R8CA01D; VOLTAGE: 50V; TOLERANCE: +/-0.25pF; Temperature Coefficient: -55C to 125C, C0G, NP0
C37 = 550-0036-000-DNI: Part Description: CAPACITOR, CERAMIC, 10NF, (DNI), +/-10%, 6.3V, -55C TO 125C, X7R, 0402 (1005 METRIC); MANUFACTURER: MURATA; PART_NUMBER: GRM155R70J103KA01D; VOLTAGE: 6.3V; TOLERANCE: +/-10%; Temperature Coefficient: -55C to 125C, X7R
C39 = 550-0041-000: Part Description: CAPACITOR, CERAMIC, 4.7UF, -20%_+80%, 10V, -30C TO 85C, Y5V, 0603 (1608 METRIC); MANUFACTURER: MURATA; PART_NUMBER: GRM188F51A475ZE20D; VOLTAGE: 10V; TOLERANCE: -20%_+80%; Temperature Coefficient: -30C to 85C, Y5V
C40 = 550-0042-000: Part Description: CAPACITOR, CERAMIC, 330PF, +/- 10%, 50V, -55C TO 125C, X7R, 0402 (1005 METRIC); MANUFACTURER: YAGEO; PART_NUMBER: CC0402KRX7R9BB331; VOLTAGE: 50V; TOLERANCE: +/- 10%; Temperature Coefficient: -55C to 125C, X7R
C41 C42 = 550-0039-000: Part Description: CAPACITOR, CERAMIC, 33PF, +/-5%, 50V, -55C TO 125C, C0G, NP0, 0402 (1005 METRIC); MANUFACTURER: SAMSUNG ELECTRONICS; PART_NUMBER: CL05C330JB5NNNC; VOLTAGE: 50V; TOLERANCE: +/-5%; Temperature Coefficient: -55C to 125C, C0G, NP0
C43 C45 = 550-0033-000-DNI: Part Description: CAPACITOR, CERAMIC, 1.0UF, (DNI), +/-10%, 10V, -55C TO 125C, X7R, 0603 (1608 METRIC); MANUFACTURER: TAIYO YUDEN LTD; PART_NUMBER: LMK107B7105KA-T; VOLTAGE: 10V; TOLERANCE: +/-10%; Temperature Coefficient: -55C to 125C, X7R
C44 = 550-0035-000-DNI: Part Description: CAPACITOR, CERAMIC, 10NF, (DNI), +/-10%, 10V, -55C TO 125C, X7R, 0402 (1005 METRIC); MANUFACTURER: KEMET; PART_NUMBER: C0402C103K8RACTU; TOLERANCE: +/-10%; VOLTAGE: 10V; Temperature Coefficient: -55C to 125C, X7R
D1-D3 = 545-0062-000: Part Description: DIODE, TVS, 45W, 5V, SOD-882; VOLTAGE: 5V; POWER: 45W
FB1 = 566-0001-000: *; Part Description: FERRITE BEAD, 60 OHM, 500MA, 0603 SMD; MANUFACTURER: MURATA; PART_NUMBER: BLM18PG600SN1D; Current Rating: 500MA
J1 = 610-0045-000-DNI: CONNECTOR, HEADER, SHROUDED, 10 POSITION, DUAL ROW, VERTICAL, 0.050"; Part Description: CONNECTOR, HEADER, FTSH-105-01-F-DV-K, (DNI), 10 POSITION, DUAL ROW, VERTICAL, 0.050IN; MANUFACTURER: SAMTEC; PART_NUMBER: FTSH-105-01-L-DV-K
J2 = 610-0086-000-DNI: 19 pin, 0.050" pitch  RCM socket, SMT; Part Description: CONNECTOR, RECEPTACLE, BD075-19, (DNI), SURFACE MOUNT VERTICAL; MANUFACTURER: GLOBAL CONNECTOR TECH; PART_NUMBER: BD075-19-A-1-L-C
J3 = 610-0087-000-DNI: 14 pin, 0.050" pitch  RCM socket, SMT; Part Description: CONNECTOR, RECEPTACLE, BD075-14, (DNI), SURFACE MOUNT VERTICAL; MANUFACTURER: GLOBAL CONNECTOR TECH; PART_NUMBER: BD075-14-A-1-L-C
J4 = 610-0081-000-DNI: U.FL RF Coaxial Connector; Part Description: CONNECTOR, RECEPTACLE, U.FL, (DNI), RF COAXIAL, SMT; MANUFACTURER: MOLEX-KOCH INDUSTRIES; PART_NUMBER: 73412-0110
J5 = 610-0105-000: Part Description: CONNECTOR, USB, 10118192-0001LF, MICRO B, SMD; MANUFACTURER: FCI
L1 = 566-2N0A-000: Design Placeholder; Part Description: INDUCTOR, METAL FILM, 2.0NH, +/-0.1NH, 220MA, -40C TO 85C, 0402 (1005 METRIC); MANUFACTURER: MURATA; PART_NUMBER: LQP15MN2N0B02D; Current Rating: 220mA; TOLERANCE: +/-0.1nH; Temperature Coefficient: -40C to 85C
L3 = 566-1N5A-000: Design Placeholder; Part Description: INDUCTOR, METAL FILM, 1.5NH, +/- 0.1NH, 280MA, -40C TO 85C, 0402 (1005 METRIC); MANUFACTURER: MURATA; PART_NUMBER: LQP15MN1N5B02D; Current Rating: 280mA; TOLERANCE: +/- 0.1nH; Temperature Coefficient: -40C to 85C
L4 = 566-3N9S-000: Design Placeholder; Part Description: INDUCTOR, MULTI-LAYER FILM, 3.9NH, +/-0.3NH, 450MA, -40C TO 85C, 0603 (1608 METRIC); MANUFACTURER: MURATA; PART_NUMBER: LQG18HN3N9S00D; Current Rating: 450mA; TOLERANCE: +/-0.3NH; Temperature Coefficient: -40C to 85C
L7 L8 = 566-2N7W-000: Design Placeholder; Part Description: INDUCTOR, WIRE WOUND, 2.7NH, +/-0.2NH, 850MA, -55C TO 125C, 0402 (1005 METRIC); MANUFACTURER: MURATA; PART_NUMBER: LQW15AN2N7C00D; Current Rating: 850mA; TOLERANCE: +/-0.2nH; Temperature Coefficient: -55C to 125C
LOGO1 = SiliconLabsLogo_100: Company Logo in PCB Title Block
PCB1 = 710-0651-006: PCB BoM ID and Top Side Silk Screen Identifier; Part Description: MECHANICAL, PCB, EM35X CERAMIC BALUN 4 LAYER REFERENCE DESIGN W/USB, INVERTED F, CORPORATE LOGO
PCB2 = 710-0651-006_ROHS: Bottom Side Silk Screen Identifier; Part Description: MECHANICAL, PCB, EM35X CERAMIC BALUN 4 LAYER REFERENCE DESIGN W/USB, INVERTED F, BOTTOM SIDE CORPORATE LOGO W/ROHS LOGO; VALUE: EM35x Ceramic Balun 4 Layer Reference Design w/USB, Inverted F, Bottom Side Corporate Logo w/ROHS logo
Q3 = 545-0047-000-DNI: MOSFET N-Channel; Part Description: MOSFET, 2N7002, (DNI), 300MA, 830MW, 60V, TO-236-3, SC-59, SOT-23-3; VOLTAGE: 60V; POWER: 830mW; Current Rating: 300mA
R1 = 555-1001-010: Part Description: RESISTOR, THICK FILM, 10 OHM, +/-1%, 0.1W, 1/10W, 0402 (1005 METRIC); MANUFACTURER: PANASONIC ECG; PART_NUMBER: ERJ-2RKF10R0X; POWER: 0.1W, 1/10W; TOLERANCE: +/-1%; Temperature Coefficient: +/-100ppm/C
R2 = 555-1R05-016: Part Description: RESISTOR, THICK FILM, 1 OHM, +/-5%, 0.1W, 1/10W, 0402 (1005 METRIC); MANUFACTURER: PANASONIC ECG; PART_NUMBER: ERJ-2GEJ1R0X; POWER: 0.1W, 1/10W; TOLERANCE: +/-5%; Temperature Coefficient: -100/ +600ppm/C
R3 R5 R7 = 555-0000-000-DNI: Part Description: RESISTOR, THICK FILM, 0_OHM, (DNI), JUMPER, 1/10W, 0402 (1005 METRIC); MANUFACTURER: SAMSUNG ELECTRONICS; PART_NUMBER: RC1005J000CS; POWER: 1/10W; TOLERANCE: Jumper; Temperature Coefficient: -100/ +600ppm/C
R8 = 555-0000-000: Part Description: RESISTOR, THICK FILM, 0_OHM, JUMPER, 1/10W, 0402 (1005 METRIC); MANUFACTURER: SAMSUNG ELECTRONICS; PART_NUMBER: RC1005J000CS; POWER: 1/10W; TOLERANCE: Jumper; Temperature Coefficient: -100/ +600ppm/C
R10 R19 R36 = 555-1045-016-DNI: Part Description: RESISTOR, THICK FILM, 100K, (DNI), +/-5%, 0.1W, 1/10W, 0402 (1005 METRIC); MANUFACTURER: PANASONIC ECG; PART_NUMBER: ERJ-2GEJ104X; POWER: 0.1W, 1/10W; TOLERANCE: +/-5%; Temperature Coefficient: +/-200ppm/C
R24 = 555-1045-016-DNI: Part Description: RESISTOR, THICK FILM, 100K, (DNI), +/-5%, 0.1W, 1/10W, 0402 (1005 METRIC); MANUFACTURER: PANASONIC ECG; PART_NUMBER: ERJ-2GEJ104X; TOLERANCE: +/-5%; POWER: 0.1W, 1/10W; Temperature Coefficient: +/-200ppm/C
R37 = 555-1045-016: Part Description: RESISTOR, THICK FILM, 100K, +/-5%, 0.1W, 1/10W, 0402 (1005 METRIC); MANUFACTURER: PANASONIC ECG; PART_NUMBER: ERJ-2GEJ104X; POWER: 0.1W, 1/10W; TOLERANCE: +/-5%; Temperature Coefficient: +/-200ppm/C
R38 = 555-0017-000: Part Description: RESISTOR, THICK FILM, 0.51 OHM, +/-1%, 0.167W, 1/6W, 0402 (1005 METRIC); MANUFACTURER: PANASONIC ECG; PART_NUMBER: ERJ-2BQFR51X; POWER: 0.167W, 1/6W; Temperature Coefficient: +/-250ppm/C; TOLERANCE: +/-1%
R39 = 555-150K-016: Part Description: RESISTOR, THICK FILM, 150K, +/-1%, 1/16W, 0402 (1005 METRIC); MANUFACTURER: SAMSUNG ELECTRONICS; PART_NUMBER: RC1005J154CS; POWER: 1/16W; TOLERANCE: +/-1%; Temperature Coefficient: +/-100ppm/C
R40 R41 = 555-33R1-010: Part Description: RESISTOR, CHIP, 33 OHM, +/-1%, 0.1W, 1/10W, 0402; MANUFACTURER: PANASONIC ECG; PART_NUMBER: ERJ-2RKF33R0X; TOLERANCE: +/-1%; POWER: 0.1W, 1/10W
R42 = 555-1521-016: Part Description: RESISTOR, 1.5K OHM, 1%, 1/16W, 0402; MANUFACTURER: PANASONIC ECG; PART_NUMBER: ERJ-2RKF1501X; POWER: 1/16W; TOLERANCE: +/-1%; Temperature Coefficient: +/-100ppm/C
U1 = 540-0358-000: IC, EM357, ZIGBEE/802.15.4 RF SOLUTION, ARM CORTEX-M3, 12K RAM, 192K FLASH, QFN-48; Part Description: IC, COMMUNICATIONS, EM358X, -40C TO 85C, SOC, ZIGBEE/802.15.4 RF TRANSCEIVER, ARM CORTEX-M3, TO 12 - 64K RAM, 128 - 512K FLASH, 48-QFN; MANUFACTURER: SILICON LABS
U3 = 500-0089-000-DNI: PART_NUMBER: AAT3220IGY-3.3-T1; Part Description: IC, LDO, (DNI), 3.3V, 150MA, -40C TO 85C, SC59; MANUFACTURER: SKYWORKS INC
U11 = 510-1039-000-DNI: IC - MEMORY, SERIAL FLASH, 2M (2M X 1, 1M X 2), 2.7 V - 3.6 V, -40C  85C, 8-SOIC (0.154", 3.90MM WIDTH); PART_NUMBER: MX25L8006EM1I-12G, MX25L8006EM1R-12G, W25Q80BVSNIG, W25Q80BVSNJG; Part Description: IC - PROGRAMMABLE MEMORY - BLANK, SERIAL FLASH, DNI, (8M X 1, 4M X 2), 2.7 V - 3.6 V, -40C  85C, 8-SOIC (0.154IN, 3.90MM WIDTH); MANUFACTURER: MACRONIX, MACRONIX, WINBOND, WINBOND
X1 = 610-0010-DNI: Part Description: CONNECTOR, INTERFACE, RCM, DEV KIT, EM35X, DUAL ROW SOCKET, (DNI)
Y1 = 565-2400-009: OSCILLATOR, CRYSTAL, 24.000MHZ, 18PF LOAD, +/-10PPM TOLERANCE, +/-25PPM STABILITY, -40C TO 85C, AT49; MANUFACTURER: ABRACON, ABRACON, ABRACON, ILSI AMERICA, AEL CRYSTALS LTD; PART_NUMBER: ABLS-24.000MHZ-D-R60-1-W-T, ABLS-24.000MHZ-D1X-T, ABLS-438-24.000MHZ-T, HC49USM-24.000000M-2435, X24M000000S067
Y2 = 565-3271-001-DNI: Part Description: OSCILLATOR, CRYSTAL, 32.768KHZ, 12.5PF, (DNI), +/-20PPM, -40C TO 85C, 2-SMD; MANUFACTURER: ABRACON, FOX CRYSTALS, ILSI AMERICA, ILSI AMERICA; PART_NUMBER: ABS07-32.768KHz-T, FX135A-327, IL3X-HX5-12.5-32.768KHz, IL3X-BX5-12.5-32.768KHz; TOLERANCE: +/-20ppm; Temperature Coefficient: -40C to 85C

## Sheet EM358x_REF_DES_CER_USB_INV-F_App.SchDoc: EM358x/0805 Ceramic Balun W/USB Reference Design
size C; Organization: MCU & Wireless Division Simplicity Support Group; Address1: 25 Thomson Place, 2nd Floor; Address2: Boston, MA 02210, USA; Address3: www.silabs.com; Address4: 617-951-0200; Revision: A0; SheetNumber: 4; SheetTotal: 5
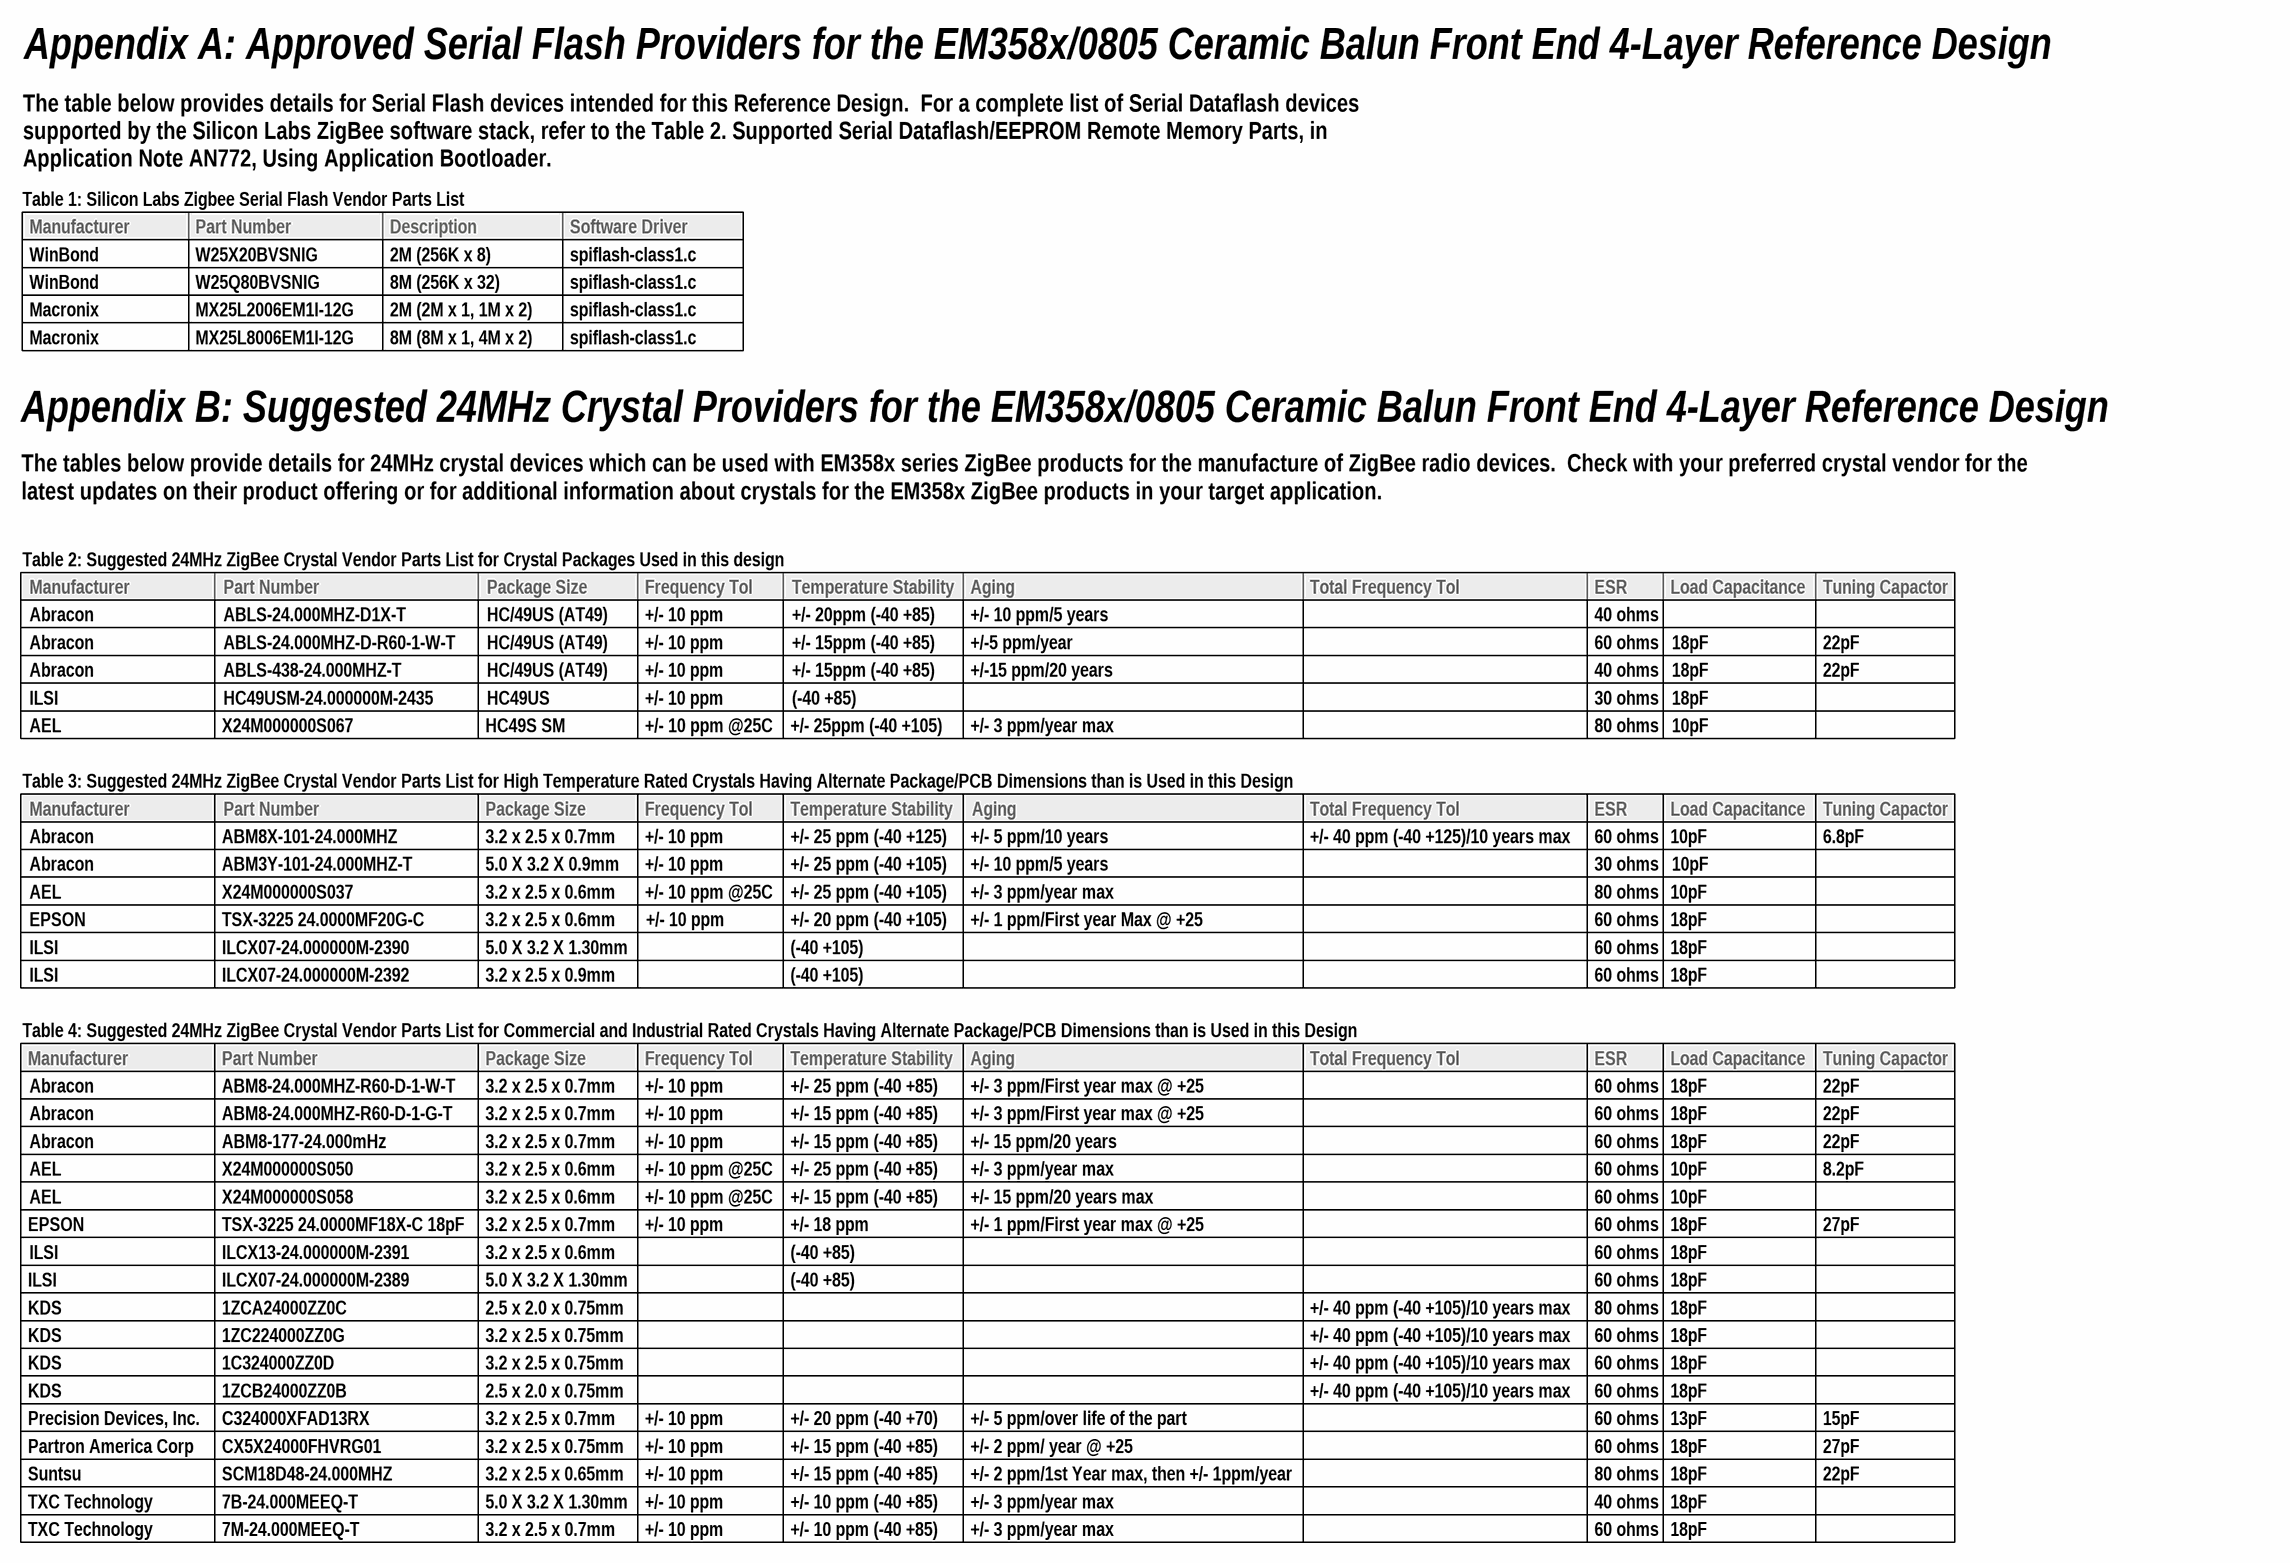
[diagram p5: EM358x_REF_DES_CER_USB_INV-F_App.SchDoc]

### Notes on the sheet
- Appendix A: Approved Serial Flash Providers for the EM358x/0805 Ceramic Balun Front End 4-Layer Reference Design
- Table 1: Silicon Labs Zigbee Serial Flash Vendor Parts List
- The table below provides details for Serial Flash devices intended for this Reference Design.  For a complete list of Serial Dataflash devices supported by the Silicon Labs ZigBee software stack, refer to the Table 2. Supported Serial Dataflash/EEPROM Remote Memory Parts, in Application Note AN772, Using Application Bootloader.
- Manufacturer
- Part Number
- Description
- Software Driver
- WinBond
- W25X20BVSNIG
- W25Q80BVSNIG
- 2M (256K x 8)
- 8M (256K x 32)
- spiflash-class1.c
- Macronix
- MX25L2006EM1I-12G
- MX25L8006EM1I-12G
- 2M (2M x 1, 1M x 2)
- 8M (8M x 1, 4M x 2)
- Appendix B: Suggested 24MHz Crystal Providers for the EM358x/0805 Ceramic Balun Front End 4-Layer Reference Design
- The tables below provide details for 24MHz crystal devices which can be used with EM358x series ZigBee products for the manufacture of ZigBee radio devices.  Check with your preferred crystal vendor for the latest updates on their product offering or for additional information about crystals for the EM358x ZigBee products in your target application.
- Table 2: Suggested 24MHz ZigBee Crystal Vendor Parts List for Crystal Packages Used in this design
- Abracon
- ABLS-24.000MHZ-D1X-T
- ABLS-24.000MHZ-D-R60-1-W-T
- Package Size
- HC/49US (AT49)
- Frequency Tol
- +/- 10 ppm
- Temperature Stability
- +/- 15ppm (-40 +85)
- +/- 20ppm (-40 +85)
- Aging
- +/- 10 ppm/5 years
- +/-5 ppm/year
- Total Frequency Tol
- ESR
- 60 ohms
- 40 ohms
- Load Capacitance
- 18pF
- Tuning Capactor
- 22pF
- ILSI
- HC49USM-24.000000M-2435
- ABLS-438-24.000MHZ-T
- HC49US
- (-40 +85)
- +/-15 ppm/20 years
- 30 ohms
- Table 3: Suggested 24MHz ZigBee Crystal Vendor Parts List for High Temperature Rated Crystals Having Alternate Package/PCB Dimensions than is Used in this Design
- AEL
- X24M000000S067
- HC49S SM
- +/- 10 ppm @25C
- +/- 25ppm (-40 +105)
- +/- 3 ppm/year max
- 80 ohms
- 10pF
- ABM8X-101-24.000MHZ
- 3.2 x 2.5 x 0.7mm
- +/- 25 ppm (-40 +125)
- +/- 5 ppm/10 years
- +/- 40 ppm (-40 +125)/10 years max
- 6.8pF
- EPSON
- ABM3Y-101-24.000MHZ-T
- X24M000000S037
- TSX-3225 24.0000MF20G-C
- 5.0 X 3.2 X 0.9mm
- 3.2 x 2.5 x 0.6mm
- +/- 25 ppm (-40 +105)
- +/- 20 ppm (-40 +105)
- +/- 1 ppm/First year Max @ +25
- ILCX07-24.000000M-2390
- ILCX07-24.000000M-2392
- 5.0 X 3.2 X 1.30mm
- 3.2 x 2.5 x 0.9mm
- (-40 +105)
- Table 4: Suggested 24MHz ZigBee Crystal Vendor Parts List for Commercial and Industrial Rated Crystals Having Alternate Package/PCB Dimensions than is Used in this Design
- ABM8-24.000MHZ-R60-D-1-G-T
- ABM8-24.000MHZ-R60-D-1-W-T
- +/- 15 ppm (-40 +85)
- +/- 25 ppm (-40 +85)
- +/- 3 ppm/First year max @ +25
- ABM8-177-24.000mHz
- X24M000000S050
- X24M000000S058
- +/- 15 ppm/20 years
- +/- 15 ppm/20 years max
- 8.2pF
- TSX-3225 24.0000MF18X-C 18pF
- ILCX13-24.000000M-2391
- +/- 18 ppm
- +/- 1 ppm/First year max @ +25
- 27pF
- KDS
- ILCX07-24.000000M-2389
- 1ZCA24000ZZ0C
- 1ZC224000ZZ0G
- 2.5 x 2.0 x 0.75mm
- 3.2 x 2.5 x 0.75mm
- +/- 40 ppm (-40 +105)/10 years max
- 1C324000ZZ0D
- 1ZCB24000ZZ0B
- Partron America Corp
- Suntsu
- Precision Devices, Inc.
- C324000XFAD13RX
- CX5X24000FHVRG01
- SCM18D48-24.000MHZ
- 3.2 x 2.5 x 0.65mm
- +/- 20 ppm (-40 +70)
- +/- 5 ppm/over life of the part
- +/- 2 ppm/ year @ +25
- +/- 2 ppm/1st Year max, then +/- 1ppm/year
- 13pF
- 15pF
- TXC Technology
- 7B-24.000MEEQ-T
- 7M-24.000MEEQ-T
- +/- 10 ppm (-40 +85)

## Sheet EM358x_REF_DES_CER_USB_INV-F_Rev_Notes.SchDoc: EM358x/0805 Ceramic Balun W/USB Reference Design
size C; Organization: MCU & Wireless Division Simplicity Support Group; Address1: 25 Thomson Place, 2nd Floor; Address2: Boston, MA 02210, USA; Address3: www.silabs.com; Address4: 617-951-0200; Revision: A0; SheetNumber: 5; SheetTotal: 5
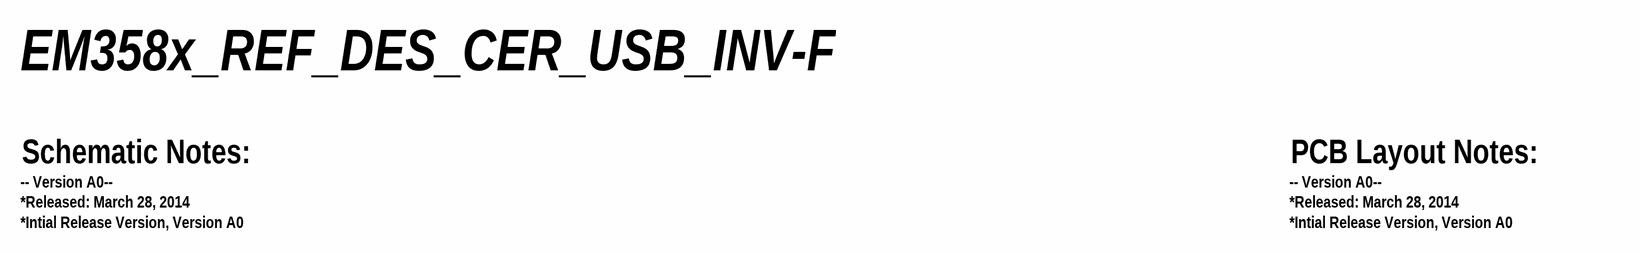
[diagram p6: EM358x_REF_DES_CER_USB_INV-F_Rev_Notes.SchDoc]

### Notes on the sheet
- EM358x_REF_DES_CER_USB_INV-F
- Schematic Notes:
- PCB Layout Notes:
- -- Version A0--
- *Released: March 28, 2014
- *Intial Release Version, Version A0

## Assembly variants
PCB0651-006_Proto_Assembly: all parts fitted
